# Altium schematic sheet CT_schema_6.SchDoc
size 274 x 160 mm
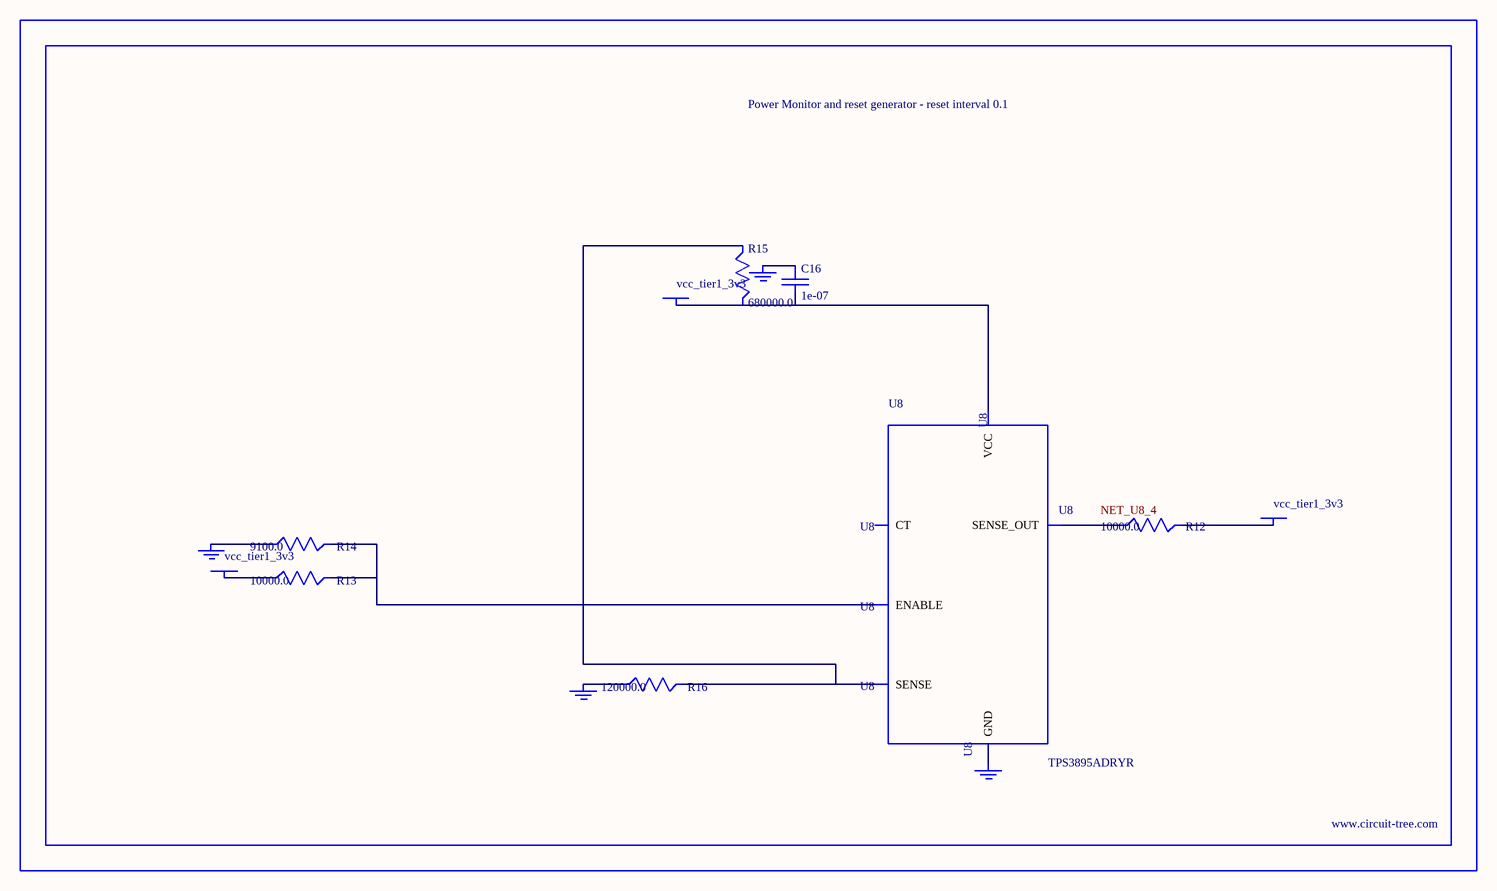
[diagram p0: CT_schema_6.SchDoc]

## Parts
BORDER5  (no value)
C16  1e-07  [C0402]
GND_INSTANCE_5_0  (no value)
GND_INSTANCE_5_1  (no value)
GND_INSTANCE_5_2  (no value)
GND_INSTANCE_5_3  (no value)
POWER_INSTANCE_5_0  vcc_tier1_3v3
POWER_INSTANCE_5_1  vcc_tier1_3v3
POWER_INSTANCE_5_2  vcc_tier1_3v3
R12  10000.0  [R0603]
R13  10000.0  [R0603]
R14  9100.0  [R0603]
R15  680000.0  [R0603]
R16  120000.0  [R0603]
U8  TPS3895ADRYR  [SON-6]

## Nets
NetC16_1: C16.1 GND_INSTANCE_5_2.0(GND)
NetC16_2: C16.2 POWER_INSTANCE_5_2.0(PWR) R15.2 U8.6(VCC)
NetGND_INSTANCE_5_0_0: GND_INSTANCE_5_0.0(GND) R14.1
NetGND_INSTANCE_5_1_0: GND_INSTANCE_5_1.0(GND) R16.1
NetGND_INSTANCE_5_3_0: GND_INSTANCE_5_3.0(GND) U8.2(GND)
NetPOWER_INSTANCE_5_0_0: POWER_INSTANCE_5_0.0(PWR) R13.1
NetPOWER_INSTANCE_5_1_0: POWER_INSTANCE_5_1.0(PWR) R12.2
NetR12_1: R12.1 U8.4(SENSE_OUT)
NetR13_2: R13.2 R14.2 U8.1(ENABLE)
NetR15_1: R15.1 R16.2 U8.3(SENSE)

Not connected (* = marked no-connect by the designer): U8 5(CT)

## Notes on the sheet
- Labels drawn without touching a wire or pin: NET_U8_4

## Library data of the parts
BORDER5 = BORDER_PAGE5
C16 = C0402C104K3RACTU
GND_INSTANCE_5_0-GND_INSTANCE_5_3 = GND
POWER_INSTANCE_5_0-POWER_INSTANCE_5_2 = PWR
R12 R13 = RC0603JR-0710KL
R14 = RC0603JR-079K1L
R15 = RC0603JR-07680KL
R16 = RC0603JR-07120KL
